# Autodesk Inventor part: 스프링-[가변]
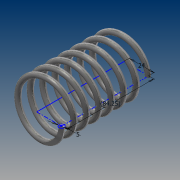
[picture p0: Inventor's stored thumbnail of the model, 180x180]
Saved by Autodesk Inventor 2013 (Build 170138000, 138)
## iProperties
Created: 2014-12
Part Number: 스프링-[가변]
Material: 강철, 탄소
Document SubType Name: Modeling
Designer: HS001
Density: 7.87 g/cm^3
Mass: 161.108 g
Surface Area: 165.536 cm^2
Volume: 20.4712 cm^3
Author: HS001
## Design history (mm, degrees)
sketch "스케치1"
  geometry: L1 (0, 0)-(24, 0); L2 (24, 0)-(24, 84.25); L3 (24, 84.25)-(0, 84.25); L4 (0, 84.25)-(0, 0); C1 r 2.5 at (24, 0)
  constraints: 8 end point, 2 parallel, 1 centre point, 1 coincident, 1 horizontal, 1 perpendicular
  dimensions: "d0" = 24 distance of L3.end L2.end; "d1" = 84.25 distance of L2.end L1.end (derived); "d2" = 5 diameter of C1
feature "코일1" pitch "d3" = 10; turns "d5" = 7; dims "d4" = 84.25 (= d1), "d6" = 0, angle "d7" = 90 deg, angle "d8" = 90 deg, "d9" = 0, "d10" = 0
sketch "스케치2"
  geometry: L1 (-26.5, 0)-(-21.5, 0) reference; L2 (-26.5, 0)-(-21.5, 0) reference; 1 further point
  constraints: 2 horizontal alignment
extrude "돌출1" cut sketch "스케치2" distance "d11" = 10; taper "d12" = 0 deg
node "작업 평면1"
sketch "스케치3"
  geometry: L1 (2.5, 0)-(-2.5, 0) reference; 1 further point
  constraints: 1 horizontal alignment
extrude "돌출2" cut sketch "스케치3" distance "d13" = 10; taper "d14" = 0 deg
node "솔리드1"
node "절단 모서리 투영1"
node "절단 모서리 투영2"
node "절단 모서리 투영3"
